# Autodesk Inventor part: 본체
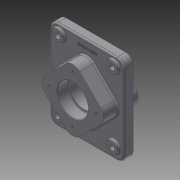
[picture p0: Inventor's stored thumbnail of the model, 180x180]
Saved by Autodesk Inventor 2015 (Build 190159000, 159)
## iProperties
Created: 2026-07
Part Number: 본체
Material: 일반
Document SubType Name: Modeling
Designer: USER
Density: 1 g/cm^3
Appearance: 기본값
Mass: 789.526 g
Surface Area: 957.533 cm^2
Volume: 789.526 cm^3
Author: USER
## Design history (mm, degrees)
sketch "스케치1"
  geometry: L1 (-75, -90)-(75, -90); L2 (75, -90)-(75, 90); L3 (75, 90)-(-75, 90); L4 (-75, 90)-(-75, -90); L5 (-75, -90)-(75, 90); L6 (75, -90)-(-75, 90); 1 further point
  constraints: 12 end point, 2 midpoint, 2 parallel, 1 horizontal, 1 perpendicular
  dimensions: "d0" = 150 distance of L1.start L1.end; "d1" = 180 distance of L1.end L2.end
extrude "돌출1" new body sketch "스케치1" stored distance "d2" = 18; taper "d3" = 0 deg
fillet "모깎기1" dims "d4" = 15
sketch "스케치5"
  geometry: L1 (0, 70.711)-(-70.711, 0); L2 (-70.711, 0)-(0, -70.711); L3 (0, -70.711)-(70.711, 0); L4 (70.711, 0)-(0, 70.711); 1 further point
  constraints: 8 end point, 2 horizontal alignment, 2 parallel, 1 perpendicular, 1 vertical alignment
  dimensions: "d9" = 100 distance of L3.end L1.start; "d10" = 100 distance of L1.start L1.end
extrude "돌출3" join sketch "스케치5" distance "d11" = 29; taper "d13" = 0 deg; dims "d12" = 41, "d14" = 0
fillet "모깎기2" dims "d15" = 20
sketch "스케치9"
  geometry: C1 r 11 at (-55, 72.853); 1 further point
  constraints: 1 centre point
  dimensions: "d18" = 22 diameter of C1; "d19" = 55 horizontal distance of point (0, 0) C1.centre
extrude "돌출4" join sketch "스케치9" distance "d20" = 5; taper "d21" = 0 deg
sketch "스케치10"
  geometry: C1 r 11 at (0, 0) reference; C2 r 11 at (110, 0) reference; C3 r 11 at (0, -140) reference; C4 r 11 at (110, -140) reference; 1 further point
hole "구멍1" sketch "스케치10" at (0, 0) diameter "d28" = 11; stored, may be unused: countersink angle "d32" = 90 deg, drill point angle "d34" = 118 deg; dims "d29" = 6, "d30" = 4, "d31" = 2, "d33" = 8
sketch "스케치11"
  geometry: 1 further point
hole "구멍2" sketch "스케치11" at (0, 0) diameter "d41" = 54; stored, may be unused: countersink angle "d45" = 90 deg, drill point angle "d47" = 118 deg; dims "d42" = 6, "d43" = 62, "d44" = 22, "d46" = 8
sketch "스케치12"
  geometry: 1 further point
hole "구멍3" sketch "스케치12" at (0, 0) diameter "d48" = 54; stored, may be unused: countersink angle "d52" = 90 deg, drill point angle "d54" = 118 deg; dims "d49" = 6, "d50" = 62, "d51" = 22, "d53" = 8
sketch "스케치15"
  geometry: L1 (0, 0)-(0, -48)
  constraints: 2 end point, 1 vertical
  dimensions: "d74" = 48 distance of L1.start L1.end
hole "구멍6" sketch "스케치15" at (0, -48) diameter "d75" = 4.917; stored, may be unused: countersink angle "d79" = 90 deg, drill point angle "d81" = 118 deg; dims "d76" = 10, "d77" = 62, "d78" = 22, "d80" = 13
sketch "스케치16"
  geometry: L1 (60, 90)-(-60, 90) reference; 2 further points
  constraints: 1 other
  dimensions: "d85" = 15 distance from line of point (1.123, 75) L1
feature "엠보싱1" sketch "스케치16" dims "d0" = 150, "d1" = 180, "d15" = 20, "d86" = 0.5, "d87" = 0
chamfer "모따기1" distance "d88" = 1; stored, may be unused: second distance "d89" = 2, angle "d90" = 45 deg
chamfer "모따기2" distance "d91" = 1; stored, may be unused: second distance "d92" = 2, angle "d93" = 45 deg
fillet "모깎기3" dims "d94" = 3
fillet "모깎기4" dims "d95" = 3
fillet "모깎기5" dims "d96" = 1
fillet "모깎기6" dims "d97" = 3
sketch "스케치17"
  geometry: L1 (0, 0)-(0, 48); C1 r 2.458 at (0, 48) reference
  constraints: 2 end point, 1 vertical
  dimensions: "d98" = 48 distance of L1.start L1.end (derived)
hole "구멍7" sketch "스케치17" at (0, 48) diameter "d99" = 4.917; stored, may be unused: countersink angle "d103" = 90 deg, drill point angle "d105" = 118 deg; dims "d100" = 10, "d101" = 62, "d102" = 22, "d104" = 13
node "솔리드1"
pattern_linear "직사각형 패턴1" dims "d24" = 110
pattern_linear "직사각형 패턴2" dims "d37" = 110
pattern_circular "원형 패턴2" dims angle "d83" = 360 deg
pattern_circular "원형 패턴3" dims angle "d107" = 360 deg
node "투영된 루프1"
node "투영된 루프2"
node "투영된 루프3"
node "투영된 루프4"
